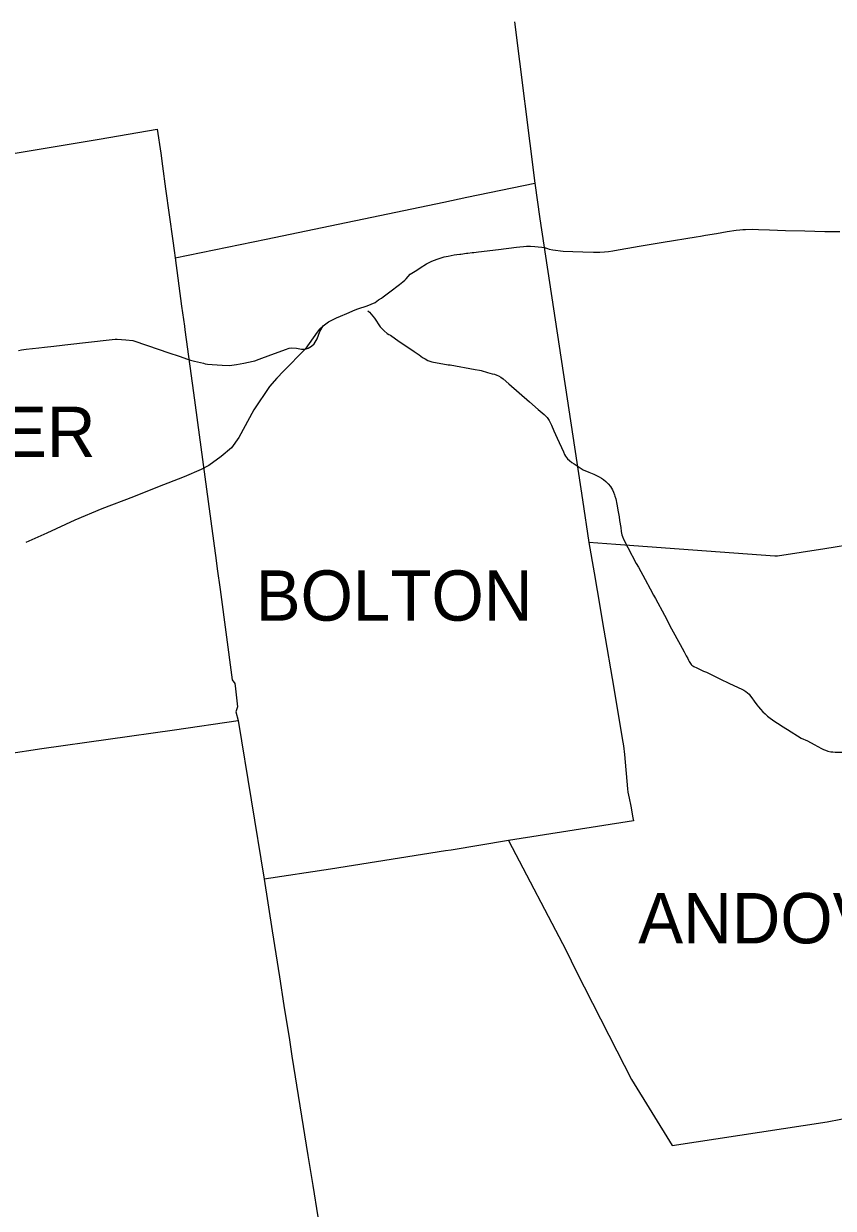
# Model space of a CAD drawing. Extents: x 0 to 2603, y -226 to 830.
# Drawn here: x 236.38 to 258.1, y 621.65 to 653.45 of the extents above; entities that cross this region are included whole.
import ezdxf

# ---------------------------------------------------------------- set-up
doc = ezdxf.new("R2010")
doc.units = 0
for name, color, linetype in [('CT_TSH_Map_Districts', 7, 'Continuous'), ('CT_TSH_Map_Interstate_Roads', 7, 'Continuous'), ('CT_TSH_Map_Town_Limits', 7, 'Continuous'), ('CT_TSH_Map_Town_Text', 7, 'Continuous'), ('CT_TSH_Map_US_and_State_Routes', 7, 'Continuous')]:
    doc.layers.add(name, color=color, linetype=linetype)

msp = doc.modelspace()

# ---------------------------------------------------------------- linework, layer by layer
at = {"layer": 'CT_TSH_Map_Districts'}
for points in [[(249.381, 631.524), (247.843, 631.271), (247.69, 631.249), (244.605, 630.76), (242.829, 630.489)], [(249.381, 631.524), (250.932, 628.57), (251.199, 628.02), (252.289, 625.883), (252.682, 625.109), (253.772, 623.343), (257.931, 623.98), (258.295, 624.047), (259.653, 624.306), (260.314, 624.419), (260.347, 624.42), (261.319, 625.079)], [(242.829, 630.489), (243.048, 629.102), (243.244, 627.867), (243.357, 627.101), (243.509, 626.175), (243.519, 626.111), (243.576, 625.739), (244.001, 623.073), (244.135, 622.27), (244.272, 621.425)]]:
    msp.add_lwpolyline(points, dxfattribs=at)
at = {"layer": 'CT_TSH_Map_Interstate_Roads'}
for points in [[(244.413, 645.344), (244.316, 645.251), (244.247, 645.167), (243.93, 644.716)], [(243.93, 644.716), (243.352, 644.119), (243.171, 643.934), (242.974, 643.715), (242.549, 643.084)], [(242.549, 643.084), (242.152, 642.342)], [(242.152, 642.342), (241.952, 642.068), (241.672, 641.837), (241.343, 641.59)], [(240.684, 641.289), (239.967, 641.009), (239.32, 640.75)], [(241.343, 641.59), (241.14, 641.486), (240.684, 641.289)], [(239.32, 640.75), (238.478, 640.424)], [(238.478, 640.424), (237.75, 640.122)], [(237.75, 640.122), (237.503, 640.007), (237.001, 639.776)], [(237.001, 639.776), (236.439, 639.524)]]:
    msp.add_lwpolyline(points, dxfattribs=at)
at = {"layer": 'CT_TSH_Map_Town_Limits'}
for points in [[(249.542, 653.499), (250.093, 649.168)], [(234.817, 652.292), (234.635, 651.113), (234.45, 649.751), (235.881, 649.926), (238.406, 650.347), (239.96, 650.616), (240.057, 649.971), (240.1, 649.622), (240.187, 649.021), (240.381, 647.624), (240.411, 647.362), (240.441, 647.163)], [(240.441, 647.163), (242.882, 647.662), (247.651, 648.655), (248.266, 648.789), (250.093, 649.168)], [(250.093, 649.168), (250.227, 648.214), (251.373, 640.667), (251.54, 639.522)], [(240.441, 647.163), (240.613, 645.863), (240.642, 645.685), (240.689, 645.328), (240.699, 645.228), (240.931, 643.545), (241.323, 640.627), (241.541, 639.045), (241.565, 638.814), (241.646, 638.259), (241.968, 635.838), (242.042, 635.738), (242.054, 635.676), (242.115, 635.116), (242.068, 634.984), (242.136, 634.75)], [(266.01, 633.215), (265.768, 633.546), (265.237, 634.301), (264.101, 635.927), (263.893, 636.232), (261.754, 639.314), (261.314, 639.935), (260.873, 639.86), (259.224, 639.582), (258.81, 639.51), (258.143, 639.4), (257.866, 639.35), (256.603, 639.155), (256.532, 639.16), (253.966, 639.346), (252.261, 639.472), (251.54, 639.522)], [(251.54, 639.522), (251.682, 638.71), (251.845, 637.765), (251.907, 637.38), (251.981, 636.964), (252.163, 635.875), (252.451, 634.17), (252.473, 634.065), (252.496, 633.835), (252.573, 632.916), (252.583, 632.822), (252.62, 632.665), (252.665, 632.445), (252.715, 632.134), (252.733, 632.053), (249.381, 631.524)], [(223.321, 631.958), (224.04, 632.071), (227.173, 632.552), (229.474, 632.901), (232.851, 633.392), (235.926, 633.848), (236.867, 633.996), (240.427, 634.496), (242.136, 634.75)], [(242.136, 634.75), (242.829, 630.489)], [(249.381, 631.524), (247.843, 631.271), (247.69, 631.249), (244.605, 630.76), (242.829, 630.489)], [(249.381, 631.524), (250.932, 628.57), (251.199, 628.02), (252.289, 625.883), (252.682, 625.109), (253.772, 623.343), (257.931, 623.98), (258.295, 624.047), (259.653, 624.306), (260.314, 624.419), (260.347, 624.42), (261.319, 625.079)], [(242.829, 630.489), (243.048, 629.102), (243.244, 627.867), (243.357, 627.101), (243.509, 626.175), (243.519, 626.111), (243.576, 625.739), (244.001, 623.073), (244.135, 622.27), (244.272, 621.425)]]:
    msp.add_lwpolyline(points, dxfattribs=at)
at = {"layer": 'CT_TSH_Map_US_and_State_Routes'}
for p, q in [((253.534, 647.589), (254.422, 647.731)), ((254.422, 647.731), (254.538, 647.75)), ((254.538, 647.75), (254.664, 647.771)), ((256.088, 647.929), (256.382, 647.917)), ((257.869, 647.872), (257.955, 647.87)), ((257.955, 647.87), (258.272, 647.875)), ((248.583, 647.325), (249.117, 647.389)), ((249.117, 647.389), (249.595, 647.449)), ((250.478, 647.401), (250.574, 647.377)), ((252.326, 647.377), (252.788, 647.46)), ((252.788, 647.46), (252.831, 647.467)), ((252.831, 647.467), (253.534, 647.589)), ((248.105, 647.265), (248.26, 647.286)), ((248.26, 647.286), (248.29, 647.29)), ((248.29, 647.29), (248.413, 647.304)), ((248.413, 647.304), (248.45, 647.308)), ((248.45, 647.308), (248.583, 647.325)), ((246.921, 646.834), (247.014, 646.894)), ((245.043, 645.673), (245.271, 645.767)), ((245.271, 645.767), (245.345, 645.796)), ((245.345, 645.796), (245.59, 645.873)), ((236.939, 644.769), (237.187, 644.797)), ((237.187, 644.797), (237.412, 644.822)), ((237.412, 644.822), (237.479, 644.83)), ((237.479, 644.83), (237.723, 644.857)), ((237.723, 644.857), (237.955, 644.884)), ((237.955, 644.884), (238.836, 644.984)), ((236.441, 644.712), (236.785, 644.751)), ((236.785, 644.751), (236.939, 644.769)), ((243.553, 644.745), (243.693, 644.74))]:
    msp.add_line(p, q, dxfattribs=at)
for points in [[(254.664, 647.771), (254.962, 647.82), (255.252, 647.87), (255.487, 647.906), (255.591, 647.916), (255.669, 647.924), (255.741, 647.929)], [(255.741, 647.929), (255.916, 647.932), (256.088, 647.929)], [(256.382, 647.917), (256.814, 647.902), (257.337, 647.885), (257.869, 647.872)], [(249.595, 647.449), (249.688, 647.459), (249.784, 647.47), (249.866, 647.475), (249.973, 647.477), (250.09, 647.47)], [(250.09, 647.47), (250.18, 647.463), (250.28, 647.448), (250.377, 647.429), (250.433, 647.416), (250.478, 647.401)], [(250.574, 647.377), (250.848, 647.345), (251.114, 647.334)], [(251.114, 647.334), (251.381, 647.324), (251.662, 647.317), (251.836, 647.317)], [(251.836, 647.317), (251.961, 647.325), (252.063, 647.335), (252.18, 647.351), (252.326, 647.377)], [(247.014, 646.894), (247.184, 647.001), (247.252, 647.043), (247.331, 647.078), (247.472, 647.132), (247.577, 647.164), (247.659, 647.189), (247.766, 647.213), (247.849, 647.23)], [(247.849, 647.23), (247.929, 647.244), (247.994, 647.254), (248.078, 647.264), (248.105, 647.265)], [(245.978, 646.086), (246.023, 646.115), (246.095, 646.168), (246.205, 646.254), (246.461, 646.451), (246.551, 646.517), (246.602, 646.562), (246.643, 646.603), (246.744, 646.724), (246.921, 646.834)], [(245.59, 645.873), (245.701, 645.917), (245.81, 645.969), (245.899, 646.033), (245.978, 646.086)], [(245.613, 645.74), (245.651, 645.703), (245.785, 645.549)], [(244.413, 645.344), (244.481, 645.397), (244.554, 645.446), (244.661, 645.503), (244.772, 645.552), (244.873, 645.598), (245.043, 645.673)], [(245.785, 645.549), (245.944, 645.316)], [(243.93, 644.716), (244.009, 644.74), (244.095, 644.79), (244.171, 644.86), (244.247, 644.991), (244.319, 645.184), (244.413, 645.344)], [(245.944, 645.316), (246.051, 645.201), (246.129, 645.134), (246.171, 645.105), (246.214, 645.085), (246.448, 644.923), (246.602, 644.819), (246.853, 644.647), (246.984, 644.558), (247.078, 644.494), (247.147, 644.451), (247.223, 644.413), (247.271, 644.392), (247.329, 644.377)], [(238.836, 644.984), (238.882, 644.986), (239.122, 644.961)], [(239.122, 644.961), (239.31, 644.943), (239.698, 644.811)], [(239.698, 644.811), (240.273, 644.616), (240.548, 644.524), (240.777, 644.448), (240.854, 644.422), (240.958, 644.394)], [(236.239, 644.681), (236.316, 644.698), (236.441, 644.712)], [(242.697, 644.442), (243.004, 644.558), (243.228, 644.638), (243.403, 644.704), (243.496, 644.738), (243.553, 644.745)], [(243.693, 644.74), (243.83, 644.717), (243.93, 644.716)], [(240.958, 644.394), (241.198, 644.338), (241.248, 644.324), (241.307, 644.313), (241.439, 644.306), (241.7, 644.287), (241.901, 644.272)], [(241.901, 644.272), (242.087, 644.3), (242.285, 644.337), (242.408, 644.361), (242.534, 644.391), (242.583, 644.404), (242.697, 644.442)], [(247.329, 644.377), (247.769, 644.295)], [(247.769, 644.295), (247.818, 644.289)], [(247.818, 644.289), (248.494, 644.171)], [(248.494, 644.171), (248.609, 644.148), (248.654, 644.14), (248.822, 644.091), (248.948, 644.053), (249.011, 644.038), (249.069, 644.018), (249.12, 643.996), (249.182, 643.959), (249.239, 643.919), (249.394, 643.782)], [(249.394, 643.782), (249.95, 643.299)], [(249.95, 643.299), (250.183, 643.097)], [(250.183, 643.097), (250.341, 642.96), (250.389, 642.917), (250.425, 642.877), (250.476, 642.798), (250.534, 642.676)], [(250.534, 642.676), (250.603, 642.524)], [(250.603, 642.524), (250.693, 642.322), (250.856, 641.96)], [(250.856, 641.96), (250.886, 641.89), (250.916, 641.841), (250.97, 641.772), (251.021, 641.722), (251.084, 641.676), (251.142, 641.639), (251.391, 641.475)], [(251.391, 641.475), (251.539, 641.408), (251.673, 641.356), (251.747, 641.324), (251.818, 641.288), (251.876, 641.251), (251.931, 641.213), (251.995, 641.159), (252.057, 641.096), (252.116, 641.026), (252.17, 640.942), (252.203, 640.872), (252.228, 640.808), (252.238, 640.769)], [(252.238, 640.769), (252.259, 640.699)], [(252.259, 640.699), (252.294, 640.549), (252.329, 640.349), (252.352, 640.216), (252.365, 640.112)], [(252.365, 640.112), (252.396, 639.929), (252.408, 639.819), (252.425, 639.734), (252.441, 639.681), (252.467, 639.61), (252.584, 639.387), (252.813, 638.963)], [(252.813, 638.963), (252.87, 638.858)], [(252.87, 638.858), (253.048, 638.528), (253.182, 638.28), (253.273, 638.11), (253.324, 638.018)], [(253.324, 638.018), (253.566, 637.57), (253.76, 637.211), (253.987, 636.785)], [(253.987, 636.785), (254.092, 636.592), (254.151, 636.486)], [(254.151, 636.486), (254.191, 636.407), (254.215, 636.366), (254.231, 636.33), (254.245, 636.302), (254.264, 636.276), (254.284, 636.254), (254.306, 636.234), (254.329, 636.216), (254.358, 636.198), (254.434, 636.162)], [(254.434, 636.162), (254.619, 636.074)], [(254.619, 636.074), (254.693, 636.041), (255.072, 635.859), (255.297, 635.751)], [(255.297, 635.751), (255.544, 635.633), (255.646, 635.584), (255.697, 635.558), (255.749, 635.527), (255.793, 635.492), (255.836, 635.453), (255.879, 635.404), (255.915, 635.355), (255.974, 635.263), (256.044, 635.168), (256.086, 635.117), (256.142, 635.05), (256.208, 634.981), (256.267, 634.926), (256.335, 634.866), (256.406, 634.809), (256.463, 634.766), (256.526, 634.723), (256.671, 634.634), (256.711, 634.606)], [(256.711, 634.606), (256.869, 634.509), (257.236, 634.274), (257.407, 634.197), (257.582, 634.107), (257.784, 633.995)], [(257.784, 633.995), (257.838, 633.969), (257.884, 633.949), (257.948, 633.928), (258.027, 633.91), (258.087, 633.902), (258.145, 633.896), (258.262, 633.898), (258.388, 633.893), (258.609, 633.883), (258.637, 633.882)]]:
    msp.add_lwpolyline(points, dxfattribs=at)

# ---------------------------------------------------------------- texts
at = {"layer": 'CT_TSH_Map_Town_Text'}
for s, p in [('MANCHESTER', (225.667, 641.82)), ('BOLTON', (242.602, 637.426)), ('ANDOVER', (252.864, 628.766))]:
    msp.add_text(s, height=1.35, dxfattribs=at).set_placement(p)

doc.saveas('drawing.dxf')
